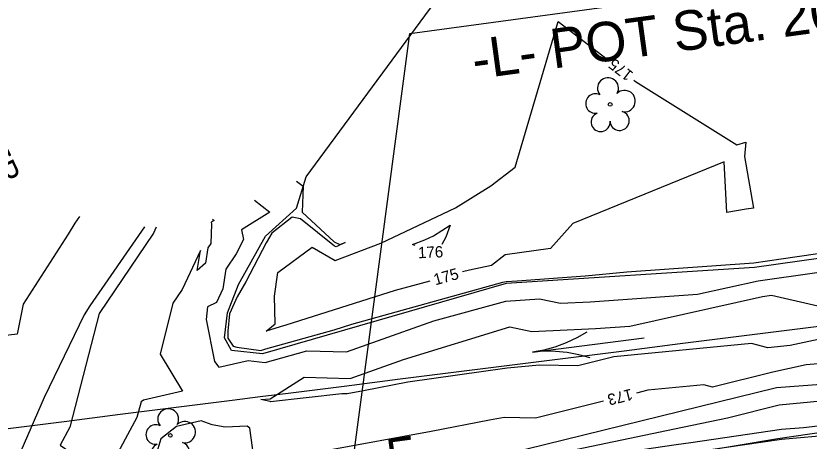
# Model space of a CAD drawing. Extents: x 2086416 to 2115205, y 575507 to 632762.
# Drawn here: x 2112066 to 2112206.5, y 581776.8 to 581852.1 of the extents above; entities that cross this region are included whole.
import ezdxf

# ---------------------------------------------------------------- set-up
doc = ezdxf.new("R2010")
doc.units = 0
for name, color, linetype in [('DTM Contours Major', 7, 'Continuous'), ('DTM Contours Major Text', 7, 'Continuous'), ('DTM Contours Minor', 7, 'Continuous'), ('DTM Contours Minor Text', 7, 'Continuous'), ('Exist Hydro River Flow Arrow CELL', 7, 'Continuous'), ('Exist Hydro Stream or Body of Water', 7, 'Continuous'), ('Exist Hydro Stream or Body of Water Text', 7, 'Continuous'), ('Exist Hydrographic FEMA Cross Section', 7, 'Continuous'), ('Exist Vegetation Tree CELL', 7, 'Continuous'), ('Exist Vegetation Woods Line', 7, 'Continuous'), ('Prop Horizontal Alignment Station Label', 7, 'Continuous'), ('Prop SS Fill Text', 7, 'Continuous')]:
    doc.layers.add(name, color=color, linetype=linetype)

# ---------------------------------------------------------------- blocks, each defined once
blk = doc.blocks.new('EXIST VEGETATION TREE')
at = {"layer": 'Exist Vegetation Tree CELL'}
blk.add_line((0, 0), (0, 0), dxfattribs=at)
blk.add_circle((0, 0), 0.00652, dxfattribs=at)
for centre, radius, start, end in [((-0.0077, 0.0575), 0.0371, 330.1651, 219.7134), ((-0.0521, 0.0031), 0.0345, 62.6636, 279.3457), ((0.051, 0.0118), 0.038, 257.1011, 134.1999), ((0.0335, -0.058), 0.034, 181.2822, 74.56), ((-0.0341, -0.0624), 0.0338, 111.5671, 6.231)]:
    blk.add_arc(centre, radius, start, end, dxfattribs=at)

msp = doc.modelspace()

# ---------------------------------------------------------------- linework, layer by layer
at = {"layer": 'DTM Contours Major'}
for points in [[(2112112.85, 581797.04), (2112110.37, 581796.22), (2112111.94, 581797.57), (2112111.83, 581802.43), (2112112.4, 581806.66), (2112118.49, 581811.14), (2112122.54, 581808.76), (2112130.66, 581811.84), (2112143.86, 581818.08), (2112150.13, 581821.98), (2112154.41, 581825.32), (2112162.03, 581851.09), (2112170.71, 581844.39)], [(2112175.46, 581840.72), (2112175.77, 581840.48), (2112193.69, 581829.27), (2112195.28, 581829.69), (2112195.05, 581827.16), (2112196.62, 581818.04), (2112195.37, 581817.87), (2112191.9, 581817.27), (2112191.46, 581826.23), (2112164.65, 581815.31), (2112160.7, 581810.9), (2112152.68, 581809.75), (2112150.22, 581807.86), (2112146.34, 581807.07), (2112145.13, 581806.73)], [(2112139.35, 581805.13), (2112133.2, 581803.43), (2112113.81, 581797.3), (2112112.85, 581797.04)], [(2112250.84, 581784.31), (2112248.78, 581784.05), (2112244.24, 581783.68), (2112231.32, 581782.17), (2112205.51, 581779.15), (2112201.62, 581778.82), (2112185.54, 581776.45), (2112182.95, 581776.14), (2112158.47, 581772.54), (2112153.21, 581771.93), (2112151.68, 581771.59)]]:
    msp.add_lwpolyline(points, dxfattribs=at)
at = {"layer": 'DTM Contours Minor'}
for points in [[(2112115.71, 581822.83), (2112116.9, 581821.9), (2112116.71, 581817.35), (2112122.36, 581812.07), (2112123.37, 581811.59), (2112124.35, 581811.93), (2112122.86, 581811.22), (2112122.73, 581811.17), (2112122.46, 581811.33), (2112116.41, 581816.13), (2112114.96, 581816.45), (2112111.37, 581813.59), (2112110.36, 581811.89), (2112106.73, 581804.97), (2112105.22, 581802.33), (2112103.86, 581799.31), (2112103.55, 581796.23), (2112103.56, 581795.03), (2112104.51, 581793.57), (2112105.15, 581793.39), (2112109.38, 581792.84), (2112110.29, 581793.14), (2112122.39, 581796.51), (2112125.49, 581797.5), (2112152.23, 581804.9), (2112152.82, 581805.02), (2112154.77, 581805.19), (2112166.81, 581806.03), (2112174.22, 581806.74), (2112196.69, 581808.35), (2112201.53, 581809.07), (2112214.14, 581810.88)], [(2112108.29, 581819.46), (2112111.02, 581817.33), (2112105.99, 581814.17), (2112106.32, 581812.51), (2112105.01, 581809.96), (2112103.2, 581807.2), (2112102.69, 581803.73), (2112101.57, 581801.33), (2112099.95, 581800.54), (2112099.75, 581798.32), (2112101.17, 581790.89), (2112101.98, 581789.87), (2112107.13, 581791.07), (2112110.16, 581790.7), (2112117.54, 581792.78), (2112124.57, 581792.57), (2112140.05, 581798.05), (2112152.79, 581801.59), (2112158.72, 581802), (2112162.44, 581801.2), (2112167.71, 581801.43), (2112186.73, 581802.78), (2112197.47, 581805.18), (2112207.84, 581806.65)], [(2112077.28, 581816.54), (2112076.49, 581815.4), (2112075.28, 581813.41), (2112067.32, 581801.05), (2112066.28, 581795.74), (2112048, 581793.55)], [(2112100.86, 581816.09), (2112101.15, 581815.87), (2112100.62, 581815.53), (2112100.69, 581815.2), (2112100.57, 581811.8), (2112100.04, 581811), (2112099.63, 581808.28), (2112098.11, 581806.98), (2112098.73, 581810.56), (2112095.48, 581803.62), (2112093.84, 581801.18), (2112091.59, 581792.2), (2112095.53, 581785.64), (2112088.63, 581784.02), (2112088.24, 581783.72), (2112087.42, 581780.96), (2112082.85, 581772.39)], [(2112088.83, 581814.72), (2112079.12, 581800.73), (2112078.14, 581799.13), (2112071.05, 581784.53), (2112066.9, 581774.98), (2112066.08, 581772.08), (2112065.42, 581771.2), (2112065.88, 581771.2), (2112064.24, 581767.51), (2112055.95, 581749.21), (2112056.11, 581747.54), (2112056.41, 581741.81), (2112056.85, 581736.91), (2112057.52, 581734.78), (2112059.14, 581725.01)], [(2112090.87, 581814.66), (2112090.38, 581813.62), (2112080.78, 581799.37), (2112080.33, 581797.56), (2112075.59, 581779.24), (2112073.89, 581776.04), (2112083.95, 581769.1), (2112085.39, 581767.32), (2112092.2, 581754.1), (2112096.77, 581742.85), (2112096.78, 581742.38), (2112097.23, 581741.37), (2112099.72, 581728.46), (2112099.68, 581727.47)], [(2112138.46, 581812.45), (2112139.96, 581813.16), (2112142.91, 581815), (2112142.18, 581812.89), (2112141.43, 581811.62)], [(2112136.75, 581811.42), (2112136.27, 581811.62), (2112138.46, 581812.45)], [(2112365.59, 581810.56), (2112361.46, 581809.99), (2112349.02, 581802.57), (2112347.6, 581803.55), (2112345.98, 581804.33), (2112345.2, 581809.49), (2112337.86, 581808.33), (2112330.84, 581808.1), (2112319.28, 581806.42), (2112300.97, 581805.74), (2112300.63, 581804.2), (2112288.06, 581801.33), (2112274.47, 581799.88), (2112256.84, 581795.79), (2112246.32, 581794.17), (2112239.46, 581793.57), (2112236.58, 581792.82), (2112224.97, 581791.88), (2112205.98, 581790.26), (2112200.06, 581788.98), (2112189.4, 581786.34), (2112187.84, 581786.74), (2112177.91, 581785.78), (2112175.91, 581785.28)], [(2112153.01, 581789.68), (2112135.42, 581787.2), (2112127.57, 581785.69), (2112124.67, 581785.16), (2112123.77, 581785.18), (2112111.09, 581783.73), (2112111.04, 581783.78), (2112109.4, 581784.14), (2112111.05, 581784.24), (2112117.07, 581788.12), (2112125.24, 581787.88), (2112134.65, 581791.21), (2112153.51, 581797.04), (2112157.38, 581796.21), (2112168.64, 581796.7), (2112174.72, 581797.13), (2112198.24, 581802.38), (2112199.85, 581802.61), (2112215.46, 581799.05), (2112243.2, 581806.99), (2112245.03, 581807.25), (2112246.64, 581807.45), (2112260.42, 581806.87)], [(2112279.92, 581804.94), (2112272.03, 581804.1), (2112268.77, 581803.34), (2112262.98, 581802.45), (2112245.58, 581798.79), (2112244.37, 581798.47), (2112217.55, 581796.31), (2112213.6, 581795.97), (2112203.11, 581793.7), (2112199.17, 581793.32), (2112196.28, 581794.07), (2112171.9, 581791.7), (2112165.55, 581790.12), (2112158.77, 581790.25), (2112153.01, 581789.68)], [(2112217.82, 581784.76), (2112201.19, 581783.13), (2112192.06, 581780.85), (2112182.63, 581778.88), (2112164.02, 581774.99), (2112153.6, 581773.46), (2112153.19, 581773.42), (2112147.81, 581772.24), (2112147.68, 581772.2), (2112118.86, 581765.87), (2112118.38, 581765.74), (2112114.81, 581764.1), (2112110.37, 581762.54), (2112109.22, 581761.56), (2112106.53, 581760.03), (2112104.59, 581757.38), (2112103.76, 581755.94), (2112103.4, 581754.72)], [(2112170.08, 581783.83), (2112158.03, 581780.84), (2112152.5, 581780.95), (2112149.88, 581780.47), (2112139.56, 581778.48), (2112120.85, 581775.08)], [(2112108.4, 581772.25), (2112107.48, 581779.07), (2112106.96, 581779.44), (2112103.09, 581779.26), (2112100.76, 581779.64), (2112098.86, 581780.38), (2112094.46, 581779.34), (2112091.7, 581777.18), (2112090.12, 581771.85)], [(2112211, 581777.89), (2112201.57, 581777.09), (2112188.62, 581775.18)]]:
    msp.add_lwpolyline(points, dxfattribs=at)
at = {"layer": 'Exist Hydro River Flow Arrow CELL'}
for p, q in [((2112167.1, 581796.07), (2112165.33, 581795.05)), ((2112157.48, 581792.53), (2112177.31, 581795.08)), ((2112165.33, 581795.05), (2112163.45, 581794.17)), ((2112159.5, 581792.87), (2112157.48, 581792.53)), ((2112161.49, 581793.44), (2112159.5, 581792.87)), ((2112163.45, 581794.17), (2112161.49, 581793.44)), ((2112167.4, 581793.8), (2112167.4, 581793.8)), ((2112159.52, 581792.72), (2112157.48, 581792.53)), ((2112161.59, 581792.67), (2112159.52, 581792.72)), ((2112163.67, 581792.46), (2112161.59, 581792.67)), ((2112165.71, 581792.08), (2112163.67, 581792.46)), ((2112167.69, 581791.54), (2112165.71, 581792.08))]:
    msp.add_line(p, q, dxfattribs=at)
at = {"layer": 'Exist Hydro Stream or Body of Water'}
for points in [[(2112117.41, 581823.6), (2112152.01, 581870.55), (2112152.35, 581889.35), (2112159.73, 581907.41), (2112163.61, 581922.72), (2112164.82, 581936.95), (2112168.08, 581951.98)], [(2112100.33, 581748.53), (2112103.12, 581756.42), (2112105.73, 581760.69), (2112110.23, 581763.66), (2112118.22, 581768.14), (2112152.91, 581774.53), (2112200.71, 581786.3), (2112247.28, 581789.73), (2112301.11, 581801.74), (2112342.55, 581803.72), (2112346.94, 581801.46), (2112350.79, 581799.08), (2112399.71, 581802.75), (2112440.35, 581810.49), (2112440.68, 581811.97), (2112437.89, 581820.2), (2112440.3, 581822.2), (2112435.86, 581828.25), (2112435.37, 581831.56), (2112437.98, 581841.01), (2112494.54, 581874.35), (2112499.44, 581880.39)], [(2112300.06, 581820.9), (2112244.2, 581814.19), (2112196.82, 581807.52), (2112152.85, 581804.67), (2112109.7, 581792.23), (2112104.21, 581792.8), (2112102.97, 581795.07), (2112103.48, 581799.48), (2112105.46, 581804.5), (2112110.25, 581813.09), (2112115.72, 581818.03), (2112117.41, 581823.6)]]:
    msp.add_lwpolyline(points, dxfattribs=at)
at = {"layer": 'Exist Hydrographic FEMA Cross Section'}
msp.add_lwpolyline([(2112213.43, 581797.74), (2112203.51, 581796.49), (2112193.59, 581795.24), (2112183.68, 581793.99), (2112173.76, 581792.73), (2112163.84, 581791.48), (2112153.93, 581790.23), (2112144.01, 581788.98), (2112134.09, 581787.73), (2112124.18, 581786.48), (2112114.26, 581785.22), (2112109.3, 581784.6), (2112104.34, 581783.97), (2112094.42, 581782.72), (2112084.51, 581781.47), (2112074.59, 581780.22), (2112064.67, 581778.97)], dxfattribs=at)
at = {"layer": 'Exist Vegetation Woods Line'}
msp.add_lwpolyline([(2112301.36, 581782.95), (2112202.06, 581766.89), (2112123.13, 581753.42), (2112119.41, 581763.53), (2112200.97, 581777.22), (2112301.44, 581791.88), (2112399.2, 581802.76), (2112436.7, 581809.61), (2112455.71, 581861.8)], dxfattribs=at)
at = {"layer": 'Prop Horizontal Alignment Station Label'}
for p, q in [((2112135.81, 581848.95), (2112267.87, 581866.97)), ((2112120.31, 581732.42), (2112135.81, 581848.95))]:
    msp.add_line(p, q, dxfattribs=at)

# ---------------------------------------------------------------- block references
at = {"layer": 'Exist Vegetation Tree CELL', "xscale": 50, "yscale": 50}
for p in [(2112171.26, 581836.4), (2112093.38, 581777.78)]:
    msp.add_blockref('EXIST VEGETATION TREE', p, dxfattribs=at)

# ---------------------------------------------------------------- texts
at = {"layer": 'DTM Contours Major Text'}
for rotation, p in [(142.3403, (2112175.49, 581841.96)), (15.4713, (2112140.31, 581804.36))]:
    msp.add_text('175', height=2, rotation=rotation, dxfattribs=at).set_placement(p)
at = {"layer": 'DTM Contours Minor Text'}
for s, rotation, p in [('176', 2.4206, (2112137.27, 581809.15)), ('173', 193.9512, (2112174.96, 581786.08))]:
    msp.add_text(s, height=2, rotation=rotation, dxfattribs=at).set_placement(p)
at = {"layer": 'Exist Hydro Stream or Body of Water Text'}
msp.add_text('BLACK RIVER', height=4, rotation=295.5556, dxfattribs=at).set_placement((2112048.15, 581853.78))
at = {"layer": 'Prop Horizontal Alignment Station Label'}
msp.add_text('-L- POT Sta. 20+05 +/-  ', height=7, rotation=7.771, dxfattribs=at).set_placement((2112147.27, 581840.84))
at = {"layer": 'Prop SS Fill Text'}
msp.add_text('F', height=6.1, rotation=7.771, dxfattribs=at).set_placement((2112132.11, 581771.03))

doc.saveas('drawing.dxf')
